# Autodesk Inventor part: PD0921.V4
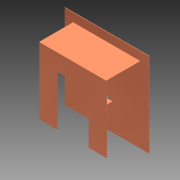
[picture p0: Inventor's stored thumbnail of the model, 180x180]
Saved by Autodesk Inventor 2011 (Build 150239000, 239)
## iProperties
Created: 2014-07
Part Number: PD0921.V4
Document SubType Name: Modeling
Designer: Evgeny
Density: 1 g/cm^3
Author: Evgeny
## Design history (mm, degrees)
sketch "Эскиз1"
  geometry: L1 (-38.25, 38.25)-(38.25, 38.25); L2 (38.25, 38.25)-(38.25, -38.25); L3 (-38.25, -38.25)-(-38.25, 38.25); L4 (-17.85, 18.25)-(17.85, 18.25); L5 (17.85, 18.25)-(17.85, -38.25); L6 (-17.85, -38.25)-(-17.85, 18.25); L7 (38.25, -38.25)-(17.85, -38.25); L8 (-17.85, -38.25)-(-38.25, -38.25); 1 further point
  constraints: 16 end point, 4 parallel, 2 horizontal, 2 perpendicular, 1 collinear
  dimensions: "d0" = 76.5 distance between parallel lines of L2 L3; "d2" = 38.25 distance from line of L3 point (0, 0); "d4" = 76.5 distance between parallel lines of L8 L1; "d5" = 38.25 distance from line of L1 point (0, 0); "d6" = 35.7 distance between parallel lines of L5 L6; "d7" = 17.85 distance from line of L6 point (0, 0); "d8" = 20 distance between parallel lines of L1 L4
extrude "Выдавливание1" new body sketch "Эскиз1" distance "d9" = 0.5; taper "d10" = 0 deg
sketch "Эскиз2"
  geometry: L1 (38.25, -38.25)-(38.25, 38.25) reference; L2 (-38.25, 38.25)-(38.25, 38.25); L3 (38.25, 38.25)-(38.25, 37.75); L4 (38.25, 37.75)-(-38.25, 37.75); L5 (-38.25, 37.75)-(-38.25, 38.25); 1 further point
  constraints: 8 end point, 2 parallel, 1 horizontal, 1 perpendicular, 1 point on line
  dimensions: "d11" = 0.5 distance between parallel lines of L4 L2
extrude "Выдавливание2" join sketch "Эскиз2" distance "d12" = 38; taper "d13" = 0 deg
sketch "Эскиз3"
  geometry: L1 (-17.85, 18.25)-(17.85, 18.25); L2 (17.85, 18.25)-(17.85, 18.75); L3 (17.85, 18.75)-(-17.85, 18.75); L4 (-17.85, 18.75)-(-17.85, 18.25); 1 further point
  constraints: 8 end point, 2 parallel, 1 horizontal, 1 perpendicular
  dimensions: "d14" = 0.5 distance between parallel lines of L1 L3; "d47" = 35.7 distance between parallel lines of L4 L2; "d48" = 17.85 distance from line of L4 point (0, 0) (derived)
extrude "Выдавливание3" join sketch "Эскиз3" distance "d15" = 19.5; taper "d16" = 0 deg
sketch "Эскиз4"
  geometry: L1 (-17.85, 18.75)-(17.85, 18.75); L2 (17.85, 18.75)-(17.85, -16.95); L3 (17.85, -16.95)-(-17.85, -16.95); L4 (-17.85, -16.95)-(-17.85, 18.75); 1 further point
  constraints: 8 end point, 2 parallel, 1 horizontal, 1 perpendicular
  dimensions: "d17" = 35.7 distance between parallel lines of L3 L1; "d18" = 35.7 distance between parallel lines of L2 L4; "d49" = 18.75 distance from line of point (0, 0) L1 (derived); "d50" = 17.85 distance from line of L2 point (0, 0) (derived)
extrude "Выдавливание4" join sketch "Эскиз4" distance "d19" = 0.5; taper "d20" = 0 deg
sketch "Эскиз5"
  geometry: L1 (17.85, -16.95)-(-17.85, -16.95) reference; L2 (-7.5, -16.95)-(7.5, -16.95); L3 (7.5, -16.95)-(7.5, -16.45); L4 (7.5, -16.45)-(-7.5, -16.45); L5 (-7.5, -16.45)-(-7.5, -16.95); 1 further point
  constraints: 8 end point, 2 parallel, 1 horizontal, 1 perpendicular, 1 point on line
  dimensions: "d21" = 0.5 distance between parallel lines of L2 L4; "d22" = 15 distance between parallel lines of L3 L5; "d23" = 7.5 horizontal distance of L2.start point (0, 0)
extrude "Выдавливание5" join sketch "Эскиз5" distance "d24" = 17; taper "d25" = 0 deg
sketch "Эскиз6"
  geometry: L1 (7.5, -16.95)-(-7.5, -16.95) reference; C1 r 1.35 at (0, -16.95); 1 further point
  constraints: 2 midpoint, 1 centre point
  dimensions: "d26" = 2.7 diameter of C1
extrude "Выдавливание6" join sketch "Эскиз6" distance "d27" = 1.5; taper "d29" = 0 deg; dims "d28" = 2, "d30" = 0
sketch "Эскиз7"
  geometry: L1 (-48, 48)-(48, 48); L2 (48, 48)-(48, -48); L3 (48, -48)-(-48, -48); L4 (-48, -48)-(-48, 48); C1 r 4.5 at (0, -17.25); 1 further point
  constraints: 8 end point, 2 parallel, 1 centre point, 1 horizontal, 1 perpendicular
  dimensions: "d32" = 96 distance of L2.end L3.end; "d33" = 96 distance between parallel lines of L3 L1; "d34" = 48 distance from line of L4 point (0, 0); "d37" = 9 diameter of C1; "d38" = 17.25 distance of C1.centre point (0, 0); "d51" = 48 distance from line of L1 point (0, 0)
extrude "Выдавливание8" join sketch "Эскиз7" distance "d39" = 0.5; taper "d40" = 0 deg
fillet "Сопряжение1" dims "d41" = 1
fillet "Сопряжение2" dims "d42" = 1
fillet "Сопряжение3" dims "d43" = 0.5
fillet "Сопряжение4" dims "d44" = 0.5
fillet "Сопряжение5" dims "d45" = 0.5
fillet "Сопряжение6" dims "d46" = 1
node "Твердое тело1"
other parameters: "d1" = 75, "d3" = 37.5
